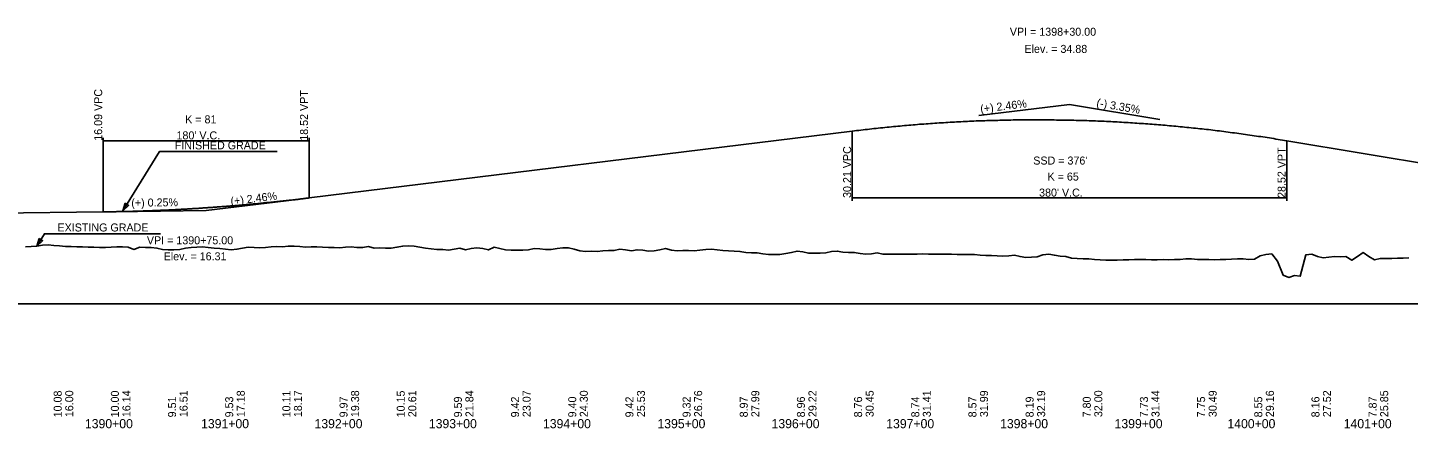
# Model space of a CAD drawing. Extents: x 2360994 to 2383826, y 330623 to 403123.
# Drawn here: x 2370444 to 2371652, y 351764 to 352114 of the extents above; entities that cross this region are included whole.
import ezdxf

# ---------------------------------------------------------------- set-up
doc = ezdxf.new("R2010")
doc.units = 0
for name, color, linetype in [('RD_DDB_GradeTX', 7, 'Continuous'), ('RD_DDB_Profile_EX', 7, 'Continuous'), ('RD_DDB_Profile_Lbl', 7, 'Continuous'), ('RD_DDB_Profile_PR', 7, 'Continuous'), ('RD_DDB_StaTX', 7, 'Continuous'), ('RD_DDB_StripGrade', 7, 'Continuous'), ('RD_DDB_VCLbl', 7, 'Continuous'), ('RD_GPK_Profile_Cell', 7, 'Continuous'), ('RD_TX_Profile', 7, 'Continuous')]:
    doc.layers.add(name, color=color, linetype=linetype)

msp = doc.modelspace()

# ---------------------------------------------------------------- linework, layer by layer
at = {"layer": 'RD_DDB_GradeTX'}
for p, q in [((2371276.2, 352037.5), (2371355.6, 352047.3)), ((2371434.5, 352034.1), (2371355.6, 352047.3)), ((2370680, 351964.2), (2370600.6, 351954.4)), ((2370520.6, 351953.4), (2370600.6, 351954.4))]:
    msp.add_line(p, q, dxfattribs=at)
at = {"layer": 'RD_DDB_Profile_EX'}
for points in [[(2370442.4, 351922.9), (2370447.4, 351923.1), (2370452.4, 351923.4), (2370457.4, 351924.1), (2370462.4, 351924.5), (2370467.4, 351924), (2370472.4, 351923.6), (2370477.4, 351923.1), (2370482.4, 351923), (2370487.4, 351922.9), (2370492.4, 351922.7), (2370497.4, 351922.6), (2370502.4, 351922.4), (2370507.4, 351922.3), (2370512.4, 351922.2), (2370517.4, 351922.4), (2370522.4, 351922.8), (2370527.4, 351922.9), (2370532.4, 351922.5), (2370537.4, 351920.5), (2370542.4, 351922.4), (2370547.4, 351922.1), (2370552.4, 351922.1), (2370557.4, 351921.7), (2370562.4, 351920.4), (2370567.4, 351920.3), (2370572.4, 351920.3), (2370577.4, 351920.5), (2370582.4, 351921.5), (2370587.4, 351922.2), (2370592.4, 351922.4), (2370597.4, 351922.7), (2370602.4, 351922.3), (2370607.4, 351921.7), (2370612.4, 351921.3), (2370617.4, 351920.6), (2370622.4, 351920.3), (2370627.4, 351920.7), (2370632.4, 351921.6), (2370637.4, 351922.5), (2370642.4, 351922.2), (2370647.4, 351921.9), (2370652.4, 351922.2), (2370657.4, 351922.8), (2370662.4, 351923), (2370667.4, 351922.9), (2370672.4, 351923.5), (2370677.4, 351923.4), (2370682.4, 351923.2), (2370687.4, 351922.6), (2370692.4, 351922.7), (2370697.4, 351922.7), (2370702.4, 351922.4), (2370707.4, 351922.3), (2370712.4, 351922.1), (2370717.4, 351922), (2370722.4, 351922.6), (2370727.4, 351922.8), (2370732.4, 351922.3), (2370737.4, 351922.1), (2370742.4, 351923), (2370747.4, 351921.7), (2370752.4, 351921.8), (2370757.4, 351921.7), (2370762.4, 351921.7), (2370767.4, 351922.4), (2370772.4, 351923.5), (2370777.4, 351923.7), (2370782.4, 351923.5), (2370787.4, 351922.5), (2370792.4, 351921.6), (2370797.4, 351920.9), (2370802.4, 351920.5), (2370807.4, 351920.4), (2370812.4, 351919.9), (2370817.4, 351920.8), (2370822.4, 351921.7), (2370827.4, 351920.3), (2370832.4, 351921.2), (2370837.4, 351921.9), (2370842.4, 351921.3), (2370847.4, 351920.1), (2370852.4, 351922.5), (2370857.4, 351921.2), (2370862.4, 351920.1), (2370867.4, 351920), (2370872.4, 351920), (2370877.4, 351920), (2370882.4, 351920.1), (2370887.4, 351921.3), (2370892.4, 351921.1), (2370897.4, 351920.4), (2370902.4, 351920.4), (2370907.4, 351921.2), (2370912.4, 351922), (2370917.4, 351921.8)], [(2370917.4, 351921.8), (2370922.4, 351920.6), (2370927.4, 351919.4), (2370932.4, 351918.7), (2370937.4, 351918.9), (2370942.4, 351918.6), (2370947.4, 351919.2), (2370952.4, 351919.6), (2370957.4, 351919.6), (2370962.4, 351920.8), (2370967.4, 351920.2), (2370972.4, 351919.4), (2370977.4, 351920.3), (2370982.4, 351920), (2370987.4, 351919.1), (2370992.4, 351919.3), (2370997.4, 351920.2), (2371002.4, 351921.3), (2371007.4, 351919.9), (2371012.4, 351919.3), (2371017.4, 351919.5), (2371022.4, 351919.5), (2371027.4, 351919.4), (2371032.4, 351920), (2371037.4, 351920.4), (2371042.4, 351920.6), (2371047.4, 351920.2), (2371052.4, 351919.7), (2371057.4, 351919.3), (2371062.4, 351919), (2371067.4, 351918.8), (2371072.4, 351917.9), (2371077.4, 351917.6), (2371082.4, 351917.4), (2371087.4, 351916.8), (2371092.4, 351916.2), (2371097.4, 351916), (2371102.4, 351916.2), (2371107.4, 351916.9), (2371112.4, 351917.9), (2371117.4, 351919.1), (2371122.4, 351918.3), (2371127.4, 351917.3), (2371132.4, 351917.2), (2371137.4, 351917.2), (2371142.4, 351917.4), (2371147.4, 351918.6), (2371152.4, 351919), (2371157.4, 351918.1), (2371162.4, 351917.9), (2371167.4, 351917.9), (2371172.4, 351917), (2371177.4, 351916.5), (2371182.4, 351916.7), (2371187.4, 351917.5), (2371192.4, 351916.5), (2371197.4, 351916.3), (2371202.4, 351916.3), (2371207.4, 351916.5), (2371212.4, 351916.3), (2371217.4, 351916.3), (2371222.4, 351916.5), (2371227.4, 351916.6), (2371232.4, 351916.4), (2371237.4, 351916.3), (2371242.4, 351916.3), (2371247.4, 351916.3), (2371252.4, 351916.3), (2371257.4, 351916.2), (2371262.4, 351916.1), (2371267.4, 351916.2), (2371272.4, 351916), (2371277.4, 351915.6), (2371282.4, 351915.3), (2371287.4, 351915.1), (2371292.4, 351914.8), (2371297.4, 351914.6), (2371302.4, 351915), (2371307.4, 351915.4), (2371312.4, 351914.2), (2371317.4, 351913.5), (2371322.4, 351913.6), (2371327.4, 351914), (2371332.4, 351915.7), (2371337.4, 351916.3), (2371342.4, 351915.4), (2371347.4, 351914.6), (2371352.4, 351914.4), (2371357.4, 351913), (2371362.4, 351912.5), (2371367.4, 351912.4), (2371372.4, 351912.2), (2371377.4, 351911.7), (2371382.4, 351911.5), (2371387.4, 351911.2), (2371392.4, 351911.1), (2371397.4, 351911.2), (2371402.4, 351911.4), (2371407.4, 351911.5), (2371412.4, 351911.6), (2371417.4, 351911.7)], [(2371417.4, 351911.7), (2371422.4, 351911.6), (2371427.4, 351911.5), (2371432.4, 351911.5), (2371437.4, 351911.6), (2371442.4, 351911.5), (2371447.4, 351911.7), (2371452.4, 351911.8), (2371457.4, 351912.2), (2371462.4, 351912.2), (2371467.4, 351911.8), (2371472.4, 351911.8), (2371477.4, 351911.6), (2371482.4, 351911.5), (2371487.4, 351911.6), (2371492.4, 351911.8), (2371497.4, 351912.1), (2371502.4, 351912.2), (2371507.4, 351912.4), (2371512.4, 351911.8), (2371517.4, 351912.1), (2371522.4, 351914.9), (2371527.4, 351916), (2371532.4, 351916.8), (2371537.4, 351910.2), (2371542.4, 351898.1), (2371547.4, 351896), (2371552.4, 351897.8), (2371557.4, 351897.1), (2371562.4, 351915.9), (2371567.4, 351916.5), (2371572.4, 351914.4), (2371577.4, 351913.2), (2371582.4, 351913.6), (2371587.4, 351914.3), (2371592.4, 351914.1), (2371597.4, 351914.3), (2371602.4, 351911.1), (2371607.4, 351914.4), (2371612.4, 351917.7), (2371617.4, 351914.3), (2371622.4, 351911.5), (2371627.4, 351912.6), (2371632.4, 351912.7), (2371637.4, 351912.7), (2371642.4, 351912.8), (2371647.4, 351912.9), (2371652.4, 351913.1)]]:
    msp.add_lwpolyline(points, dxfattribs=at)
at = {"layer": 'RD_DDB_Profile_PR'}
for p, q in [((2370690.6, 351965.5), (2371165.6, 352023.9)), ((2371545.6, 352015.5), (2371830.6, 351967.8)), ((2370403.6, 351952), (2370510.6, 351953.3))]:
    msp.add_line(p, q, dxfattribs=at)
for points in [[(2371165.6, 352023.9), (2371173.2, 352024.8), (2371180.8, 352025.7), (2371188.4, 352026.5), (2371196, 352027.3), (2371203.6, 352028), (2371211.2, 352028.7), (2371218.8, 352029.4), (2371226.4, 352030), (2371234, 352030.5), (2371241.6, 352031.1), (2371249.2, 352031.5), (2371256.8, 352032), (2371264.4, 352032.3), (2371272, 352032.7), (2371279.6, 352033), (2371287.2, 352033.2), (2371294.8, 352033.4), (2371302.4, 352033.6), (2371310, 352033.7), (2371317.6, 352033.8), (2371325.2, 352033.8), (2371332.8, 352033.8), (2371340.4, 352033.7), (2371348, 352033.6), (2371355.6, 352033.5), (2371363.2, 352033.3), (2371370.8, 352033.1), (2371378.4, 352032.8), (2371386, 352032.5), (2371393.6, 352032.1), (2371401.2, 352031.7), (2371408.8, 352031.2), (2371416.4, 352030.7), (2371424, 352030.2), (2371431.6, 352029.6), (2371439.2, 352029), (2371446.8, 352028.3), (2371454.4, 352027.6), (2371462, 352026.8), (2371469.6, 352026), (2371477.2, 352025.2), (2371484.8, 352024.3), (2371492.4, 352023.3), (2371500, 352022.3), (2371507.6, 352021.3), (2371515.2, 352020.2), (2371522.8, 352019.1), (2371530.4, 352018), (2371538, 352016.7), (2371545.6, 352015.5)], [(2370510.6, 351953.3), (2370514.2, 351953.4), (2370517.8, 351953.4), (2370521.4, 351953.5), (2370525, 351953.6), (2370528.6, 351953.6), (2370532.2, 351953.7), (2370535.8, 351953.8), (2370539.4, 351953.9), (2370543, 351954), (2370546.6, 351954.2), (2370550.2, 351954.3), (2370553.8, 351954.4), (2370557.4, 351954.6), (2370561, 351954.7), (2370564.6, 351954.9), (2370568.2, 351955), (2370571.8, 351955.2), (2370575.4, 351955.4), (2370579, 351955.6), (2370582.6, 351955.8), (2370586.2, 351956), (2370589.8, 351956.2), (2370593.4, 351956.4), (2370597, 351956.7), (2370600.6, 351956.9), (2370604.2, 351957.2), (2370607.8, 351957.4), (2370611.4, 351957.7), (2370615, 351958), (2370618.6, 351958.2), (2370622.2, 351958.5), (2370625.8, 351958.8), (2370629.4, 351959.1), (2370633, 351959.4), (2370636.6, 351959.8), (2370640.2, 351960.1), (2370643.8, 351960.4), (2370647.4, 351960.8), (2370651, 351961.1), (2370654.6, 351961.5), (2370658.2, 351961.8), (2370661.8, 351962.2), (2370665.4, 351962.6), (2370669, 351963), (2370672.6, 351963.4), (2370676.2, 351963.8), (2370679.8, 351964.2), (2370683.4, 351964.6), (2370687, 351965.1), (2370690.6, 351965.5)]]:
    msp.add_spline(points, degree=3, dxfattribs=at)
at = {"layer": 'RD_DDB_VCLbl'}
for p, q in [((2371165.6, 351963), (2371165.6, 352023.9)), ((2370510.6, 352018), (2370510.6, 351953.3)), ((2370510.6, 352015.5), (2370690.6, 352015.5)), ((2370690.6, 352018), (2370690.6, 351965.5)), ((2371545.6, 351963), (2371545.6, 352015.5)), ((2371165.6, 351965.5), (2371545.6, 351965.5))]:
    msp.add_line(p, q, dxfattribs=at)
at = {"layer": 'RD_GPK_Profile_Cell'}
msp.add_line((2368825.6, 351872.9), (2374525.6, 351872.9), dxfattribs=at)
at = {"layer": 'RD_TX_Profile'}
for p, q in [((2370662.7, 352006), (2370568.1, 352006)), ((2370560.6, 351934.2), (2370465.5, 351934.2))]:
    msp.add_line(p, q, dxfattribs=at)
for points in [[(2370568.1, 352006), (2370559.7, 352006), (2370527.6, 351954.2)], [(2370465.5, 351934.2), (2370459.1, 351934.2), (2370452.4, 351923.4)]]:
    msp.add_lwpolyline(points, dxfattribs=at)
for points in [[(2370529.6, 351960.9), (2370527.6, 351954.2), (2370532.7, 351959)], [(2370454.4, 351930), (2370452.4, 351923.4), (2370457.5, 351928.1)]]:
    msp.add_lwpolyline(points, close=True, dxfattribs=at)

# ---------------------------------------------------------------- texts
at = {"layer": 'RD_DDB_GradeTX'}
for s, rotation, p in [('(+) 2.46%', 7.0122, (2371278, 352039.8)), ('(-) 3.35%', 350.5, (2371378.8, 352045.4)), ('(+) 0.25%', 0.7102, (2370535.1, 351957.8)), ('(+) 2.46%', 7.0122, (2370622.3, 351959.1))]:
    msp.add_text(s, height=7, rotation=rotation, dxfattribs=at).set_placement(p)
at = {"layer": 'RD_DDB_Profile_Lbl'}
for s, p in [('VPI = 1398+30.00', (2371303.4, 352107.3)), ('Elev. = 34.88', (2371316.2, 352092.3)), ('VPI = 1390+75.00', (2370548.7, 351925)), ('Elev. = 16.31', (2370563.4, 351911))]:
    msp.add_text(s, height=7, dxfattribs=at).set_placement(p)
at = {"layer": 'RD_DDB_StaTX'}
for s, p in [('1390+00', (2370494.5, 351764.2)), ('1391+00', (2370596.1, 351764.2)), ('1392+00', (2370695.3, 351764.2)), ('1393+00', (2370795.3, 351764.2)), ('1394+00', (2370895.1, 351764.2)), ('1395+00', (2370995.2, 351764.2)), ('1396+00', (2371095, 351764.2)), ('1397+00', (2371195.3, 351764.2)), ('1398+00', (2371294.9, 351764.2)), ('1399+00', (2371395, 351764.2)), ('1400+00', (2371493.7, 351764.2)), ('1401+00', (2371595.4, 351764.2))]:
    msp.add_text(s, height=8, dxfattribs=at).set_placement(p)
at = {"layer": 'RD_DDB_StripGrade'}
for s, p in [('16.09 VPC', (2370509.6, 352015.5)), ('18.52 VPT', (2370689.6, 352015.5)), ('30.21 VPC', (2371164.6, 351965.5)), ('28.52 VPT', (2371544.6, 351965.5)), ('10.08', (2370474.2, 351773.7)), ('16.00', (2370484.3, 351773.9)), ('10.00', (2370524.2, 351773.7)), ('16.14', (2370534.3, 351773.9)), ('16.51', (2370584.3, 351773.9)), ('17.18', (2370634.3, 351773.9)), ('10.11', (2370674.2, 351773.7)), ('18.17', (2370684.3, 351773.9)), ('19.38', (2370734.3, 351773.9)), ('10.15', (2370774.2, 351773.7)), ('20.61', (2370784.3, 351773.9)), ('21.84', (2370834.3, 351773.9)), ('23.07', (2370884.3, 351773.9)), ('24.30', (2370934.3, 351773.9)), ('25.53', (2370984.3, 351773.9)), ('26.76', (2371034.3, 351773.9)), ('27.99', (2371084.3, 351773.9)), ('29.22', (2371134.3, 351773.9)), ('30.45', (2371184.3, 351773.9)), ('31.41', (2371234.3, 351773.9)), ('31.99', (2371284.3, 351773.9)), ('32.19', (2371334.3, 351773.9)), ('32.00', (2371384.3, 351773.9)), ('31.44', (2371434.3, 351773.9)), ('30.49', (2371484.3, 351773.9)), ('29.16', (2371534.3, 351773.9)), ('27.52', (2371584.3, 351773.9)), ('25.85', (2371634.3, 351773.9)), ('9.51', (2370574.2, 351773.7)), ('9.53', (2370624.2, 351773.7)), ('9.97', (2370724.2, 351773.7)), ('9.59', (2370824.2, 351773.7)), ('9.42', (2370874.2, 351773.7)), ('9.40', (2370924.2, 351773.7)), ('9.42', (2370974.2, 351773.7)), ('9.32', (2371024.2, 351773.7)), ('8.97', (2371074.2, 351773.7)), ('8.96', (2371124.2, 351773.7)), ('8.76', (2371174.2, 351773.7)), ('8.74', (2371224.2, 351773.7)), ('8.57', (2371274.2, 351773.7)), ('8.19', (2371324.2, 351773.7)), ('7.80', (2371374.2, 351773.7)), ('7.73', (2371424.2, 351773.7)), ('7.75', (2371474.2, 351773.7)), ('8.55', (2371524.2, 351773.7)), ('8.16', (2371574.2, 351773.7)), ('7.87', (2371624.2, 351773.7))]:
    msp.add_text(s, height=7, rotation=90, dxfattribs=at).set_placement(p)
at = {"layer": 'RD_DDB_VCLbl'}
for s, p in [('K = 81', (2370582.2, 352030.7)), ("180' V.C.", (2370574.6, 352016.7)), ("SSD = 376'", (2371323.9, 351994.7)), ('K = 65', (2371336.4, 351980.7)), ("380' V.C.", (2371329, 351966.7))]:
    msp.add_text(s, height=7, dxfattribs=at).set_placement(p)
at = {"layer": 'RD_TX_Profile'}
for s, p in [('FINISHED GRADE', (2370573.1, 352008)), ('EXISTING GRADE', (2370470.5, 351936.2))]:
    msp.add_text(s, height=7, dxfattribs=at).set_placement(p)

doc.saveas('drawing.dxf')
